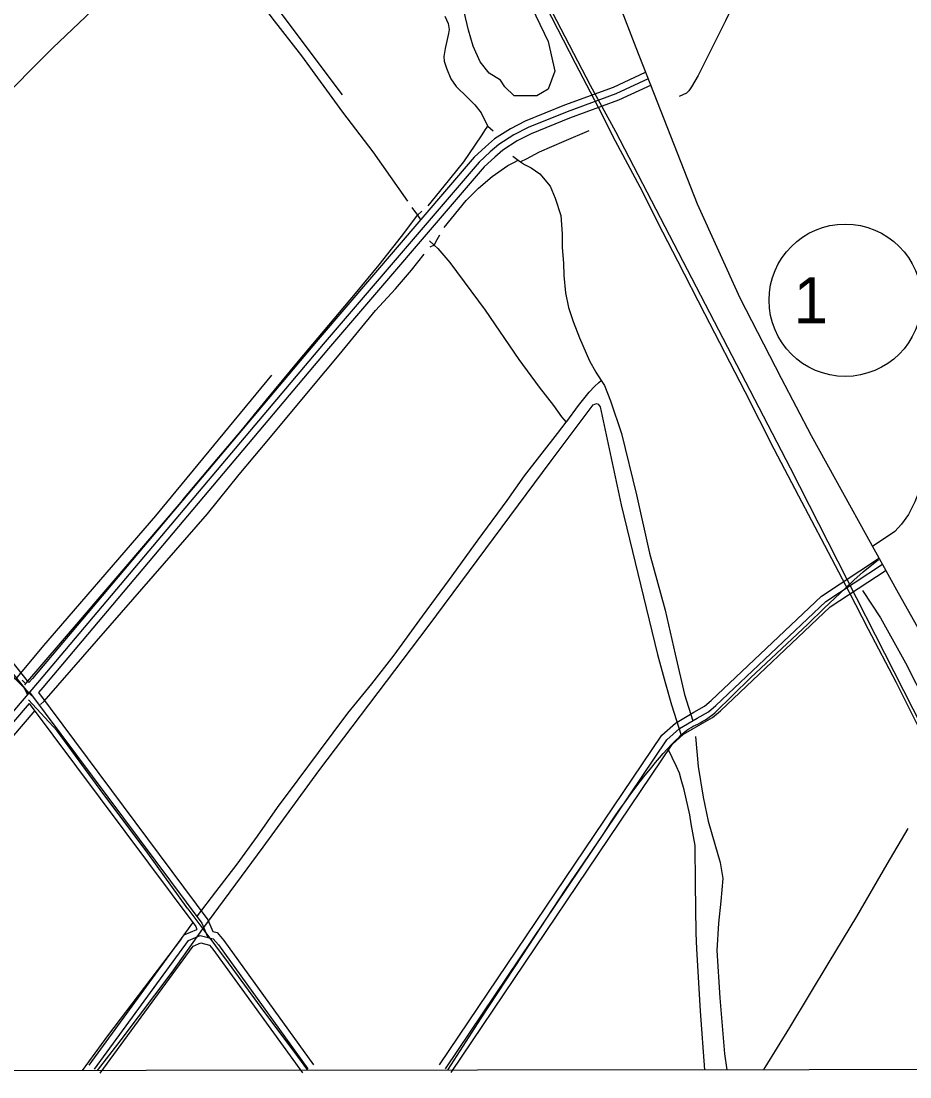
# Model space of a CAD drawing. Extents: x 3297772 to 3335630, y 634068 to 659439.
# Drawn here: x 3315244 to 3317167, y 639447 to 641733 of the extents above; entities that cross this region are included whole.
import ezdxf

# ---------------------------------------------------------------- set-up
doc = ezdxf.new("R2010")
doc.units = 0
for name, color, linetype in [('V-DTCH-CNTR', 7, 'Continuous'), ('V-GRID-FRAM', 7, 'Continuous'), ('V-RAIL-TRAK', 7, 'Continuous'), ('V-ROAD-CNTR', 7, 'Continuous'), ('V-ROAD-IDEN', 7, 'Continuous'), ('V-SITE-VEGE', 7, 'Continuous'), ('V-TOPO-SHOR', 7, 'Continuous')]:
    doc.layers.add(name, color=color, linetype=linetype)

msp = doc.modelspace()

# ---------------------------------------------------------------- linework, layer by layer
at = {"layer": 'V-DTCH-CNTR'}
msp.add_line((3315570.8, 639673.3), (3315636.7, 639767.4), dxfattribs=at)
for points in [[(3315627.4, 641979.4), (3315646.2, 641967), (3315760.4, 641811.8), (3315938.5, 641573.4)], [(3315184.3, 641547.6), (3315312.3, 641675.1), (3315454, 641810.6), (3315556.3, 641911.4), (3315594.5, 641947.7)], [(3315267.1, 640271.8), (3315232.1, 640307.3), (3315231.2, 640308.3), (3315188.5, 640357.1), (3315081.6, 640500.8), (3314960.9, 640654.2), (3314842.4, 640808.8), (3314742.3, 640941.4), (3314667.4, 641043.2), (3314586.8, 641145.4), (3314480.8, 641288.1), (3314374.1, 641424.9), (3314264.7, 641570.9), (3314182.3, 641677.4)], [(3315785.3, 640966.3), (3315534.5, 640661.5), (3315292.2, 640380.9), (3315231.2, 640308.3)], [(3315888.4, 640109.3), (3316125, 640421.7), (3316390.7, 640781), (3316482, 640902.2), (3316489, 640904.9), (3316493.1, 640903.5), (3316497.2, 640898), (3316542.2, 640685.5), (3316621.4, 640361.2), (3316637.7, 640300.5), (3316651.4, 640252.1), (3316672.2, 640187)], [(3316166.9, 639461.1), (3316168.1, 639462.8), (3316239.6, 639574), (3316328.2, 639708.7), (3316422.9, 639853.4), (3316501.9, 639969.1), (3316511.5, 639984.1), (3316521.2, 639999.1), (3316531.2, 640013.9), (3316541.3, 640028.6), (3316551.6, 640043.2), (3316562.1, 640057.6), (3316572.7, 640071.9), (3316583.6, 640086.1), (3316594.6, 640100.1), (3316605.8, 640114), (3316617.2, 640127.8), (3316625.4, 640137.4), (3316633.7, 640146.9), (3316642.2, 640156.2), (3316643.9, 640158), (3316650.8, 640165.4), (3316659.6, 640174.4), (3316668.5, 640183.3), (3316672.4, 640187.1), (3316676.4, 640190.7), (3316680.5, 640194.1), (3316684.8, 640197.4), (3316689.3, 640200.4), (3316693.8, 640203.3), (3316698.5, 640206), (3316703.3, 640208.5), (3316708.2, 640210.8), (3316713.9, 640213.7), (3316719.6, 640216.9), (3316725.1, 640220.2), (3316730.5, 640223.7), (3316735.8, 640227.5), (3316740.9, 640231.4), (3316745.9, 640235.5), (3316822.8, 640310.8), (3316946.5, 640426.9), (3316981.7, 640461.9), (3317004.8, 640483.4), (3317016.9, 640494.4), (3317030.4, 640507.3), (3317046.5, 640522.4), (3317066.6, 640540.4), (3317099.8, 640566.9)], [(3315604.5, 639810.5), (3315518.1, 639930.9), (3315414.9, 640069.3), (3315321.7, 640195.8), (3315259.8, 640263.2)], [(3316723.9, 639461.6), (3316714, 639589.1), (3316706.1, 639723.6), (3316704.8, 639758.1), (3316703.7, 639865.6), (3316702.5, 639947.7), (3316694.4, 639994.6), (3316691, 640013.9), (3316678.7, 640068.4), (3316672.6, 640090.5), (3316668.5, 640104.3), (3316662.3, 640118.8), (3316643.9, 640158)], [(3315636.7, 639767.4), (3315767.3, 639944.1), (3315888.4, 640109.3)], [(3315604.5, 639810.5), (3315636.7, 639767.4), (3315691.5, 639693.9), (3315762.5, 639596.9), (3315841.9, 639490.9), (3315863.3, 639460.8)], [(3315409.2, 639460.3), (3315460.3, 639527), (3315570.8, 639673.3)]]:
    msp.add_lwpolyline(points, dxfattribs=at)
at = {"layer": 'V-GRID-FRAM'}
msp.add_lwpolyline([(3301870.2, 657630.6), (3333425.5, 657662.7), (3333452, 639478.7), (3301880.8, 639446.5), (3301870.2, 657630.6)], dxfattribs=at)
at = {"layer": 'V-RAIL-TRAK'}
msp.add_lwpolyline([(3317571, 639462.5), (3317564.3, 639475.3), (3317514.3, 639572.2), (3317460.4, 639677.1), (3317408.5, 639778.3), (3317343.7, 639902.4), (3317292.3, 640002.6), (3317236.1, 640107.6), (3317188.4, 640200.5), (3317138, 640301.2), (3317077.9, 640415.3), (3317036.5, 640495.8), (3316983.1, 640597.4), (3316927.4, 640704.3), (3316874, 640805.9), (3316811.2, 640930.5), (3316723.5, 641099.3), (3316665.4, 641213.3), (3316632.5, 641276.1), (3316583.5, 641373.4), (3316530.1, 641473.1), (3316492.5, 641547.9), (3316443.9, 641641.8), (3316379.6, 641766.5)], dxfattribs=at)
at = {"layer": 'V-ROAD-CNTR'}
for points in [[(3319670.7, 645880.8), (3318994.9, 644472.8), (3318285.6, 643011.9), (3317900.8, 642211.9), (3317247.2, 640864.1), (3317219.6, 640803.7), (3317209.4, 640778.3), (3317196.6, 640737.1), (3317178, 640691.8), (3317164.8, 640664.4), (3317149.4, 640643.5), (3317134.6, 640627.6), (3317086.8, 640595.1)], [(3314291.1, 645810.9), (3314532.6, 645348.2), (3314722.5, 644984.4), (3314911.8, 644615.5), (3315083.1, 644279.1), (3315123.8, 644211.7), (3315381.2, 643713.7), (3315604.6, 643279.8), (3316205.3, 642114), (3316321, 641892.3), (3316475.5, 641594.6), (3316530.5, 641494.3), (3316908.1, 640765.9), (3317235.2, 640123.1), (3317563.4, 639492.7), (3317577.5, 639465.5)], [(3316169.6, 643125.7), (3316453.9, 642053.7), (3316496.7, 641904.7), (3316537.1, 641773.4), (3316574.3, 641676.1), (3316620.8, 641558.1), (3316706.7, 641337.8), (3316799.3, 641133.6), (3316888.9, 640959.6), (3316953.5, 640835.8), (3317142.2, 640495.1), (3317527.9, 639808.4)], [(3315257.7, 640274.4), (3315250.9, 640288.3), (3315260.1, 640277.3), (3315049.5, 640540.5), (3314796.8, 640866.6), (3314679.6, 641019.6), (3314663.9, 641037.4), (3314656.6, 641051.5), (3314650.7, 641062.2), (3314520.1, 641231.2), (3314315.1, 641499.4), (3314144.9, 641723.4), (3314136, 641735), (3314103.2, 641758.6), (3313858.4, 641984.9), (3313717.2, 642121.8), (3313586.1, 642261.4), (3313107.1, 642732.9)], [(3315260.5, 640300.9), (3315061.3, 640549.7), (3314808.6, 640875.8), (3314691.2, 641029.1), (3314676.4, 641045.9), (3314669.8, 641058.6), (3314663.3, 641070.4), (3314532, 641240.3), (3314327, 641508.5), (3314160.6, 641727.5)], [(3316601, 641608.4), (3316530.9, 641575.9), (3316425.5, 641537), (3316341.2, 641502.6), (3316310.1, 641486.9), (3316277.5, 641465.9), (3316258.8, 641449.8), (3316234.9, 641428), (3315897.8, 641033.9), (3315279.4, 640299.9), (3315038.3, 640017.9)], [(3316594.7, 641622), (3316525.2, 641589.8), (3316420.1, 641551), (3316335, 641516.3), (3316302.7, 641499.9), (3316268.5, 641478), (3316248.9, 641461), (3316224.1, 641438.5), (3315886.4, 641043.6), (3315268, 640309.6), (3315260.5, 640300.9)], [(3316607.3, 641594.8), (3316536.7, 641562), (3316431, 641523), (3316347.4, 641489), (3316317.6, 641473.8), (3316286.5, 641453.9), (3316268.8, 641438.6), (3316245.7, 641417.5), (3315909.3, 641024.2), (3315290.9, 640290.2), (3315281.3, 640279)], [(3316149.6, 639472.5), (3316630.3, 640186.7), (3316659.9, 640213), (3316699.9, 640236.4), (3316722.8, 640249.6), (3316737.1, 640262), (3316976.4, 640488), (3317099.8, 640569.2)], [(3316162.1, 639464.1), (3316641.7, 640176.7), (3316668.8, 640200.8), (3316707.4, 640223.4), (3316731.5, 640237.3), (3316747.2, 640250.9), (3316985.8, 640476.2), (3317108.1, 640556.7)], [(3316174.5, 639455.7), (3316653.1, 640166.8), (3316677.6, 640188.6), (3316715, 640210.4), (3316740.3, 640225.1), (3316757.2, 640239.7), (3316995.1, 640464.4), (3317116.3, 640544.2)], [(3315262.1, 640279.7), (3315634.8, 639779.4), (3315647.9, 639748.4)], [(3315281.3, 640279), (3315648, 639786.9), (3315658.8, 639761.2)], [(3315261.3, 640255.6), (3315049.1, 640007.4), (3315016.8, 639978), (3314971.6, 639929.4), (3314919, 639880.2), (3314877.9, 639854.8), (3314863.8, 639847.2)], [(3315261.3, 640255.6), (3315621.7, 639771.9), (3315624.3, 639765.7)], [(3315390.7, 639472.2), (3315596.5, 639754), (3315624.3, 639765.7)], [(3315658.8, 639761.2), (3315667.9, 639758.9), (3315682.5, 639741.8), (3315876.7, 639472.6)], [(3315402.8, 639463.3), (3315606.1, 639741.8), (3315631.5, 639752.5), (3315659.6, 639745.5), (3315670.7, 639732.5), (3315864.6, 639463.8)], [(3315415, 639454.5), (3315615.8, 639729.6), (3315632.7, 639736.7), (3315651.3, 639732.1), (3315658.9, 639723.3), (3315852.4, 639455)]]:
    msp.add_lwpolyline(points, dxfattribs=at)
at = {"layer": 'V-ROAD-IDEN'}
msp.add_circle((3317027.6, 641128.7), 165, dxfattribs=at)
at = {"layer": 'V-SITE-VEGE'}
msp.add_lwpolyline([(3316163.3, 642151.2), (3316384.4, 641689.1), (3316399.1, 641625.2), (3316384.4, 641585.9), (3316359.8, 641571.1), (3316310.7, 641571.1), (3316291, 641590.8), (3316281.2, 641605.5), (3316256.6, 641620.3), (3316237, 641644.8), (3316222.2, 641679.3), (3316212.4, 641713.7), (3316202.6, 641753)], dxfattribs=at)
at = {"layer": 'V-TOPO-SHOR'}
for p, q in [((3316091.5, 641299.1), (3316101.4, 641312.6)), ((3316101.4, 641312.6), (3316110.7, 641321.4)), ((3316137.9, 641248.1), (3316128.6, 641243.4)), ((3315590.8, 639746.3), (3315615.1, 639780))]:
    msp.add_line(p, q, dxfattribs=at)
for points in [[(3317422.9, 643102.4), (3317360.4, 642969.6), (3317301.9, 642848.9), (3317228.3, 642696.6), (3317183.4, 642598.9), (3317129.9, 642491.7), (3317083.6, 642395), (3317035.6, 642293.8), (3316984.2, 642188.1), (3316925.2, 642060.9), (3316868.7, 641942.1), (3316816.3, 641834.4), (3316768.4, 641733.8), (3316735.6, 641669.1), (3316708.9, 641615.5), (3316694.8, 641591), (3316689.3, 641582.5), (3316683.7, 641577), (3316668.2, 641570.1)], [(3315628.7, 641951.3), (3315706.2, 641848.3), (3315786.7, 641740.7), (3315850.6, 641658.3), (3315939.6, 641536.2), (3316005.1, 641450.3), (3316079.9, 641343.2)], [(3316160.5, 641743.8), (3316168, 641728.3), (3316170, 641715.2), (3316169, 641706.2), (3316161.9, 641674.1), (3316158.8, 641656.6), (3316159.3, 641646.5), (3316164.3, 641631), (3316173.7, 641608.4), (3316185.7, 641591.8), (3316209.7, 641567.6), (3316225.8, 641551.6), (3316239.8, 641534.5), (3316253.2, 641506.3), (3316253.6, 641506), (3316265.5, 641495.9)], [(3316124.6, 641333.2), (3316159.4, 641375.7), (3316202.2, 641428.7), (3316226.3, 641464.3), (3316241.9, 641486.8), (3316247.5, 641496.3), (3316253.6, 641506)], [(3316472.7, 641495.4), (3316418.1, 641472.3), (3316365.4, 641449.4), (3316336.8, 641434.4), (3316324.9, 641428.7)], [(3316159.7, 641286.5), (3316207.2, 641344.7), (3316233.8, 641371.2), (3316263, 641396.7), (3316297.2, 641420.2), (3316310.2, 641426.7), (3316319.9, 641432.2)], [(3316308.2, 641440.4), (3316319.9, 641432.2), (3316324.9, 641428.7), (3316333.3, 641422.9), (3316347.8, 641415.8), (3316366.3, 641402.2), (3316388.8, 641375.6), (3316399.8, 641350), (3316412.2, 641312.3), (3316414.6, 641272.2), (3316414.6, 641243.1), (3316418, 641209), (3316418.4, 641182.4), (3316421.8, 641144.8), (3316428.3, 641112.7), (3316438.7, 641082.6), (3316452.2, 641046.9), (3316474.1, 640997.7), (3316487.6, 640973.1), (3316499.3, 640955.1), (3316506.6, 640944), (3316519.5, 640910.8), (3316543.4, 640840), (3316575.7, 640707), (3316604, 640581.1), (3316637.8, 640457.6), (3316659.6, 640361.8), (3316679.4, 640274.9), (3316697.7, 640217.9)], [(3316089.3, 641329.5), (3316101.4, 641312.6), (3316107.1, 641304.5)], [(3315593.4, 640696.5), (3315659.3, 640774.6), (3315720.2, 640845.6), (3315775, 640912.7), (3315844, 640996.8), (3315909.4, 641074.4), (3315967.2, 641143.4), (3316018.5, 641205.5), (3316066.8, 641267.1), (3316091.5, 641299.1)], [(3316137.9, 641248.1), (3316144.3, 641260.1), (3316149.8, 641270.6)], [(3316127.7, 641257), (3316137.9, 641248.1), (3316145.8, 641241.1), (3316171.8, 641210.5), (3316248.3, 641107), (3316321.3, 641000.4), (3316364.8, 640940.6), (3316395.8, 640900.9), (3316413.3, 640876.3), (3316423.2, 640864.3)], [(3315647.2, 640666.3), (3315715.7, 640751.4), (3315783.6, 640831.9), (3315872.6, 640939.5), (3315932, 641010.6), (3316011, 641106.7), (3316053.7, 641153.3), (3316088.9, 641193.8), (3316115.8, 641228.4)], [(3315625.5, 639795), (3315664.8, 639847.5), (3315711.6, 639907.5), (3315755.4, 639968.1), (3315798.6, 640030.2), (3315843.4, 640089.8), (3315887.7, 640148.9), (3315950.6, 640234), (3316002.5, 640297.5), (3316051.3, 640360.1), (3316112.7, 640444.7), (3316170.6, 640523.8), (3316233, 640609.9), (3316295.9, 640695), (3316333.1, 640748.1), (3316404.6, 640840.2), (3316423.2, 640864.3), (3316424.7, 640866.2), (3316449.9, 640900.8), (3316473.5, 640929.8), (3316485.1, 640941.8), (3316494.1, 640950.3), (3316499.3, 640955.1)], [(3315593.4, 640696.5), (3315466.2, 640546.7), (3315328.5, 640385.7), (3315253.1, 640298.7), (3315250.7, 640295.9)], [(3315285.4, 640253.2), (3315293.7, 640260.5), (3315436.2, 640424), (3315647.2, 640666.3)], [(3317065, 640499.8), (3317104, 640441), (3317157.9, 640343), (3317203.8, 640253.6), (3317240.3, 640175.3), (3317260.2, 640133.8), (3317264.7, 640124.6), (3317310.2, 640046.7), (3317363.1, 639953.8), (3317424, 639845.8), (3317475.4, 639757.4), (3317508.9, 639683.6), (3317529.8, 639637.4)], [(3315245.8, 640306.1), (3315253.1, 640298.7), (3315254.2, 640297.5)], [(3314881.5, 639833), (3314886.9, 639833.8), (3314896.8, 639840.1), (3314906.5, 639846.5), (3314916.2, 639853.2), (3314925.7, 639860), (3314935.1, 639867), (3314944.3, 639874.2), (3314953.4, 639881.5), (3314962.4, 639889), (3314971.2, 639896.7), (3314979.9, 639904.5), (3314988.5, 639912.5), (3314996.9, 639920.7), (3315005.1, 639929), (3315013.2, 639937.5), (3315021.1, 639946.1), (3315117.8, 640057.4), (3315274.3, 640240.1)], [(3316703.2, 640183.5), (3316709.1, 640118.9), (3316720, 640052.1), (3316730.9, 640000.4), (3316745.3, 639950.3), (3316756.8, 639910.6), (3316762.7, 639876.5), (3316758, 639826.8), (3316753.4, 639779.7), (3316749.8, 639720), (3316756, 639617.7), (3316766.2, 639496.3), (3316771.1, 639461.7)], [(3317163, 639984.5), (3317117.7, 639907.2), (3317052.1, 639794), (3316992.1, 639695), (3316907.2, 639553.7), (3316853.8, 639466.9), (3316850.8, 639461.8)], [(3315590.8, 639746.3), (3315430.7, 639535.1), (3315375.7, 639460.3)]]:
    msp.add_lwpolyline(points, dxfattribs=at)

# ---------------------------------------------------------------- texts
at = {"layer": 'V-ROAD-IDEN'}
msp.add_text(' 1 ', height=100, rotation=0.0735, dxfattribs=at).set_placement((3316878.9, 641078.5))

doc.saveas('drawing.dxf')
